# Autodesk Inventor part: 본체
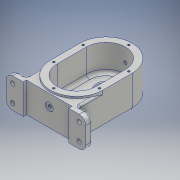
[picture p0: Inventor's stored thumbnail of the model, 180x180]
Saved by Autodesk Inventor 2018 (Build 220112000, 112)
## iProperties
Created: 2021-05
Part Number: 본체
Material: 알루미늄 6061
Document SubType Name: Modeling
Designer: Admin
Density: 2.7 g/cm^3
Appearance: 알루미늄 - 평지
Mass: 755.991 g
Surface Area: 583.745 cm^2
Volume: 279.996 cm^3
Author: Admin
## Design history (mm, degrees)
sketch "스케치1"
  geometry: L1 (-56, 0)-(56, 0) reference; L2 (0, -87.5)-(0, 87.5) reference; L3 (0, 22.5)-(0, -22.5); L4 (-40, 22.5)-(-40, -22.5); L5 (40, -22.5)-(40, 22.5); A1 r 40 centre (0, 22.5) between (40, 22.5) and (-40, 22.5); A2 r 40 centre (0, -22.5) between (-40, -22.5) and (40, -22.5); 2 further points
  constraints: 8 end point, 4 point on circle, 4 tangent, 2 centre point, 2 point on line, 1 midpoint, 1 parallel, 1 symmetric about line
  dimensions: "d0" = 45 distance of L5.start L5.end; "d1" = 80 distance between parallel lines of L5 L4
extrude "돌출1" new body sketch "스케치1" stored distance "d2" = 49; taper "d3" = 0 deg
sketch "스케치2"
  geometry: L1 (-40, -22.5)-(-40, 22.5) reference; L2 (40, 22.5)-(40, -22.5) reference; L3 (0, -87.5)-(0, 87.5) reference; L4 (-56, 0)-(56, 0) reference; L5 (-40, -22.5)-(-40, 22.5) reference; L6 (-40, -59.5)-(-61, -59.5); L7 (-61, -59.5)-(-61, -69.5); L8 (-61, -69.5)-(-35, -69.5); L9 (-35, -69.5)-(-35, -64.5); L10 (-35, -64.5)-(35, -64.5); L11 (35, -64.5)-(35, -69.5); L12 (35, -69.5)-(61, -69.5); L13 (61, -69.5)-(61, -59.5); L14 (61, -59.5)-(40, -59.5); L15 (-40, -59.5)-(-40, -22.5); L16 (40, 22.5)-(40, -22.5) reference; L17 (40, -22.5)-(40, -59.5); A1 r 40 centre (0, 22.5) between (40, 22.5) and (-40, 22.5) reference; A2 r 40 centre (0, -22.5) between (-40, -22.5) and (40, -22.5) reference; 1 further point
  constraints: 22 end point, 8 perpendicular, 3 symmetric about line, 1 horizontal, 1 point on line, 1 vertical
  dimensions: "d4" = 10 distance of L6.end L7.end; "d6" = 122 distance between parallel lines of L13 L7; "d7" = 70 distance of L9.end L10.end; "d8" = 5 distance between parallel lines of L12 L10; "d51" = 47 distance from line of L2.end L12
extrude "돌출2" join sketch "스케치2" distance "d9" = 21.5; taper "d11" = 0 deg; dims "d10" = 24.5, "d12" = 0
sketch "스케치3"
  geometry: L1 (40, -59.5)-(40, 22.5) reference; L2 (-40, 22.5)-(-40, -59.5) reference; L3 (-40, -59.5)-(-61, -59.5) reference; L4 (-61, -59.5)-(-61, -69.5) reference; L5 (-61, -69.5)-(-35, -69.5) reference; L6 (-35, -69.5)-(-35, -64.5) reference; L7 (-35, -64.5)-(35, -64.5) reference; L8 (35, -64.5)-(35, -69.5) reference; L9 (35, -69.5)-(61, -69.5) reference; L10 (61, -69.5)-(61, -59.5) reference; L11 (61, -59.5)-(40, -59.5) reference; L12 (0, -107.9)-(0, 90.9) reference; L13 (85.4, 0)-(-85.4, 0) reference; L14 (0, 22.5)-(0, -22.5); L15 (-26, 22.5)-(-26, -22.5); L16 (26, -22.5)-(26, 22.5); A1 r 40 centre (0, 22.5) between (40, 22.5) and (-40, 22.5) reference; A2 r 26 centre (0, 22.5) between (26, 22.5) and (-26, 22.5); A3 r 26 centre (0, -22.5) between (-26, -22.5) and (26, -22.5); 2 further points
  constraints: 8 end point, 4 point on circle, 4 tangent, 2 centre point, 2 point on line, 1 midpoint, 1 parallel, 1 symmetric about line
  dimensions: "d13" = 52 distance between parallel lines of L16 L15; "d14" = 45 distance of L14.end L14.start
extrude "돌출3" join sketch "스케치3" distance "d16" = 11; taper "d17" = 0 deg
sketch "스케치4"
  geometry: L1 (-40, 22.5)-(-40, -22.5) reference; L2 (40, -22.5)-(40, 22.5) reference; L3 (0, -107.9)-(0, 90.9) reference; L4 (-85.4, 0)-(85.4, 0) reference; L5 (0, 22.5)-(0, -22.5); L6 (-30, 22.5)-(-30, -22.5); L7 (30, -22.5)-(30, 22.5); A1 r 40 centre (0, -22.5) between (-40, -22.5) and (40, -22.5) reference; A2 r 40 centre (0, 22.5) between (40, 22.5) and (-40, 22.5) reference; A3 r 30 centre (0, 22.5) between (30, 22.5) and (-30, 22.5); A4 r 30 centre (0, -22.5) between (-30, -22.5) and (30, -22.5); 2 further points
  constraints: 8 end point, 4 point on circle, 4 tangent, 2 centre point, 2 point on line, 1 midpoint, 1 parallel, 1 symmetric about line
  dimensions: "d18" = 45 distance of L5.end L5.start; "d19" = 30 radius of A3
extrude "돌출4" cut sketch "스케치4" distance "d20" = 41; taper "d21" = 0 deg
sketch "스케치5"
  geometry: L1 (-30, -22.5)-(-30, 22.5) reference; L2 (30, 22.5)-(30, -22.5) reference; A1 r 30 centre (0, -22.5) between (-30, -22.5) and (30, -22.5) reference; A2 r 30 centre (0, 22.5) between (30, 22.5) and (-30, 22.5) reference; 2 further points
  constraints: 1 coincident
hole "구멍1" sketch "스케치5" at (0, 22.5) diameter "d22" = 22; stored, may be unused: countersink angle "d26" = 90 deg, drill point angle "d28" = 0 deg; dims "d23" = 6, "d24" = 28, "d25" = 8, "d27" = 12
sketch "스케치6"
  geometry: L1 (-30, -22.5)-(-30, 22.5) reference; L2 (30, 22.5)-(30, -22.5) reference; C1 r 14 at (0, 22.5) reference; A1 r 30 centre (0, -22.5) between (-30, -22.5) and (30, -22.5) reference; A2 r 30 centre (0, 22.5) between (30, 22.5) and (-30, 22.5) reference; 2 further points
  constraints: 1 coincident
hole "구멍2" sketch "스케치6" at (0, -22.5) diameter "d29" = 20; stored, may be unused: countersink angle "d33" = 90 deg, drill point angle "d35" = 0 deg; dims "d30" = 6, "d31" = 28, "d32" = 8, "d34" = 12
sketch "스케치7"
  geometry: L1 (-26, 22.5)-(-26, -22.5) reference; L2 (26, -22.5)-(26, 22.5) reference; L3 (-26, -22.5)-(-26, 22.5) reference; L4 (-26, -7.5)-(26, -7.5); L5 (26, -7.5)-(26, 66.934); L6 (26, 66.934)-(-26, 66.934); L7 (-26, 66.934)-(-26, -7.5); A1 r 26 centre (0, -22.5) between (-26, -22.5) and (26, -22.5) reference; A2 r 26 centre (0, 22.5) between (26, 22.5) and (-26, 22.5) reference; 2 further points
  constraints: 8 end point, 2 parallel, 2 point on line, 1 horizontal, 1 midpoint, 1 perpendicular
  dimensions: "d36" = 30 distance from line of L4 L2.end
extrude "돌출5" cut sketch "스케치7" distance "d37" = 3; taper "d38" = 0 deg
sketch "스케치8"
  geometry: L1 (-26, -7.5)-(-26, 22.5) reference; L2 (26, -7.5)-(-26, -7.5) reference; L3 (26, 22.5)-(26, -7.5) reference; A1 r 26 centre (0, 22.5) between (26, 22.5) and (-26, 22.5) reference; 2 further points
  constraints: 1 coincident
hole "구멍3" sketch "스케치8" at (0, 22.5) diameter "d39" = 28; stored, may be unused: countersink angle "d43" = 90 deg, drill point angle "d45" = 0 deg; dims "d40" = 6, "d41" = 28, "d42" = 8, "d44" = 4
node "작업 평면2"
  node "작업 평면1"
sketch "스케치9"
  geometry: L1 (85.4, 0)-(-85.4, 0) reference; L2 (0, -47.5)-(0, 36.5) reference; L3 (40, 24.5)-(-40, 24.5) reference; C1 r 6 at (0, 3.5); 1 further point
  constraints: 1 centre point, 1 point on line
  dimensions: "d47" = 12 diameter of C1; "d48" = 21 distance from line of C1.centre L3
extrude "돌출6" join sketch "스케치9" stored distance "d49" = 3; taper "d50" = 0 deg
sketch "스케치10"
  geometry: C1 r 6 at (0, 0) reference; 2 further points
  constraints: 1 coincident
hole "구멍4" sketch "스케치10" at (0, 0) diameter "d52" = 4.917; stored, may be unused: countersink angle "d56" = 90 deg, drill point angle "d58" = 0 deg; dims "d53" = 17, "d54" = 28, "d55" = 8, "d57" = 17.1
sketch "스케치11"
  geometry: L1 (-30, -22.5)-(-30, 22.5) reference; L2 (30, 22.5)-(30, -22.5) reference; L3 (-40, 22.5)-(-40, -22.5) reference; L4 (40, -22.5)-(40, 22.5) reference; L5 (0, -96.5)-(0, 92.5) reference; L6 (-85.4, 0)-(85.4, 0) reference; L7 (0, 22.5)-(0, -22.5); L8 (-35, 22.5)-(-35, -22.5); L9 (35, -22.5)-(35, 22.5); A1 r 30 centre (0, -22.5) between (-30, -22.5) and (30, -22.5) reference; A2 r 30 centre (0, 22.5) between (30, 22.5) and (-30, 22.5) reference; A3 r 40 centre (0, -22.5) between (-40, -22.5) and (40, -22.5) reference; A4 r 40 centre (0, 22.5) between (40, 22.5) and (-40, 22.5) reference; A5 r 35 centre (0, 22.5) between (35, 22.5) and (-35, 22.5); A6 r 35 centre (0, -22.5) between (-35, -22.5) and (35, -22.5); 8 further points
  constraints: 8 end point, 5 point on circle, 4 symmetric about line, 4 tangent, 3 point on line, 2 centre point, 2 coincident, 1 midpoint, 1 parallel
  dimensions: "d59" = 45 distance of L7.end L7.start; "d60" = 35 radius of A5
hole "구멍5" sketch "스케치11" at (0, 57.5), (0, -57.5), (35, 22.5), (35, -22.5), (-35, 22.5), (-35, -22.5) diameter "d61" = 3.242; stored, may be unused: countersink angle "d65" = 90 deg, drill point angle "d67" = 118 deg; dims "d62" = 8, "d63" = 28, "d64" = 8, "d66" = 10
sketch "스케치12" dims "d68" = 40
  geometry: L1 (0, -96.5)-(0, 92.5) reference; C1 r 11 at (0, 22.5) reference; 5 further points
  constraints: 1 coincident, 1 point on line, 1 vertical alignment, 6 other
  dimensions: "d71" = 360 deg dimension on C1.centre point (0, 42.5) (derived)
hole "구멍6" sketch "스케치12" at (0, 42.5), (-17.321, 12.5), (17.321, 12.5) diameter "d73" = 3.242; stored, may be unused: countersink angle "d77" = 90 deg, drill point angle "d79" = 118 deg; dims "d74" = 8, "d75" = 28, "d76" = 8, "d78" = 10
sketch "스케치13"
  geometry: L1 (35, -69)-(35, 15) reference; L2 (75, 3)-(-5, 3) reference; 2 further points
  constraints: 1 point on line
  dimensions: "d80" = 21 distance from line of point (35, -18) L2
hole "구멍7" sketch "스케치13" at (35, -18) diameter "d81" = 12; stored, may be unused: countersink angle "d85" = 90 deg, drill point angle "d87" = 0 deg; dims "d82" = 8, "d83" = 28, "d84" = 8, "d86" = 1
sketch "스케치14"
  geometry: C1 r 6 at (0, 0) reference; 2 further points
  constraints: 1 coincident
hole "구멍8" sketch "스케치14" at (0, 0) diameter "d89" = 4.917; stored, may be unused: countersink angle "d93" = 90 deg, drill point angle "d95" = 0 deg; dims "d90" = 17, "d91" = 28, "d92" = 8, "d94" = 17.1
fillet "모깎기1" dims "d88" = 10
sketch "스케치15"
  geometry: L1 (-21, 10)-(-21, 36) reference; L2 (0, 0)-(-11, 0) reference; L3 (0, 0)-(0, 46) reference; L4 (-11, 46)-(0, 46) reference; L5 (101, 10)-(101, 36) reference; L6 (80, 46)-(91, 46) reference; L7 (80, 0)-(80, 46) reference; L8 (91, 0)-(80, 0) reference; A1 r 10 centre (-11, 36) between (-11, 46) and (-21, 36) reference; A2 r 10 centre (-11, 10) between (-21, 10) and (-11, 0) reference; A3 r 10 centre (91, 10) between (91, 0) and (101, 10) reference; A4 r 10 centre (91, 36) between (101, 36) and (91, 46) reference; 5 further points
  constraints: 4 coincident
hole "구멍9" sketch "스케치15" at (-11, 36), (-11, 10), (91, 10), (91, 36) diameter "d96" = 6.6; stored, may be unused: countersink angle "d100" = 90 deg, drill point angle "d102" = 0 deg; dims "d97" = 17, "d98" = 11, "d99" = 2, "d101" = 17.1
chamfer "모따기1" distance "d103" = 1; stored, may be unused: second distance "d104" = 2, angle "d105" = 45 deg
fillet "모깎기2" dims "d106" = 0.3
fillet "모깎기3" dims "d107" = 3
fillet "모깎기4" dims "d108" = 5
node "작업 평면3"
sketch "스케치16"
  geometry: L1 (-51, -62.5)-(-43, -62.5) reference; L2 (-51, -69.5)-(-51, -62.5) reference; L3 (-51, -69.5)-(-35, -69.5) reference; L4 (-35, -69.5)-(-35, -64.5) reference; L5 (-35, -64.5)-(35, -64.5) reference; L6 (35, -64.5)-(35, -69.5) reference; L7 (35, -69.5)-(51, -69.5) reference; L8 (51, -62.5)-(51, -69.5) reference; L9 (43, -62.5)-(51, -62.5) reference; L10 (37, 22.5)-(37, -56.5) reference; L11 (-37, -56.5)-(-37, 22.5) reference; L12 (-29, 22.5)-(-29, -22.5) reference; L13 (29, -22.5)-(29, 22.5) reference; L14 (0, -96.506)-(0, 92.534) reference; L15 (85.4, 0)-(-85.4, 0) reference; A1 r 6 centre (43, -56.5) between (37, -56.5) and (43, -62.5) reference; A2 r 37 centre (0, 22.5) between (37, 22.5) and (-37, 22.5) reference; A3 r 6 centre (-43, -56.5) between (-43, -62.5) and (-37, -56.5) reference; A4 r 29 centre (0, 22.5) between (29, 22.5) and (-29, 22.5) reference; A5 r 29 centre (0, -22.5) between (-29, -22.5) and (29, -22.5) reference; 2 further points
  constraints: 1 point on line, 1 other
  dimensions: "d110" = 12 distance from line of L3 point (0, -57.5)
feature "엠보싱1" sketch "스케치16" dims "d111" = 0.5, "d112" = 0
node "솔리드1"
node "투영된 루프1"
node "투영된 루프2"
node "투영된 루프3"
node "투영된 루프4"
node "투영된 루프5"
node "투영된 루프6"
node "투영된 루프7"
node "투영된 루프8"
node "투영된 루프9"
node "투영된 루프10"
node "투영된 루프11"
node "투영된 루프12"
node "투영된 루프13"
other parameters: "d46" = 3, "d109" = 5
